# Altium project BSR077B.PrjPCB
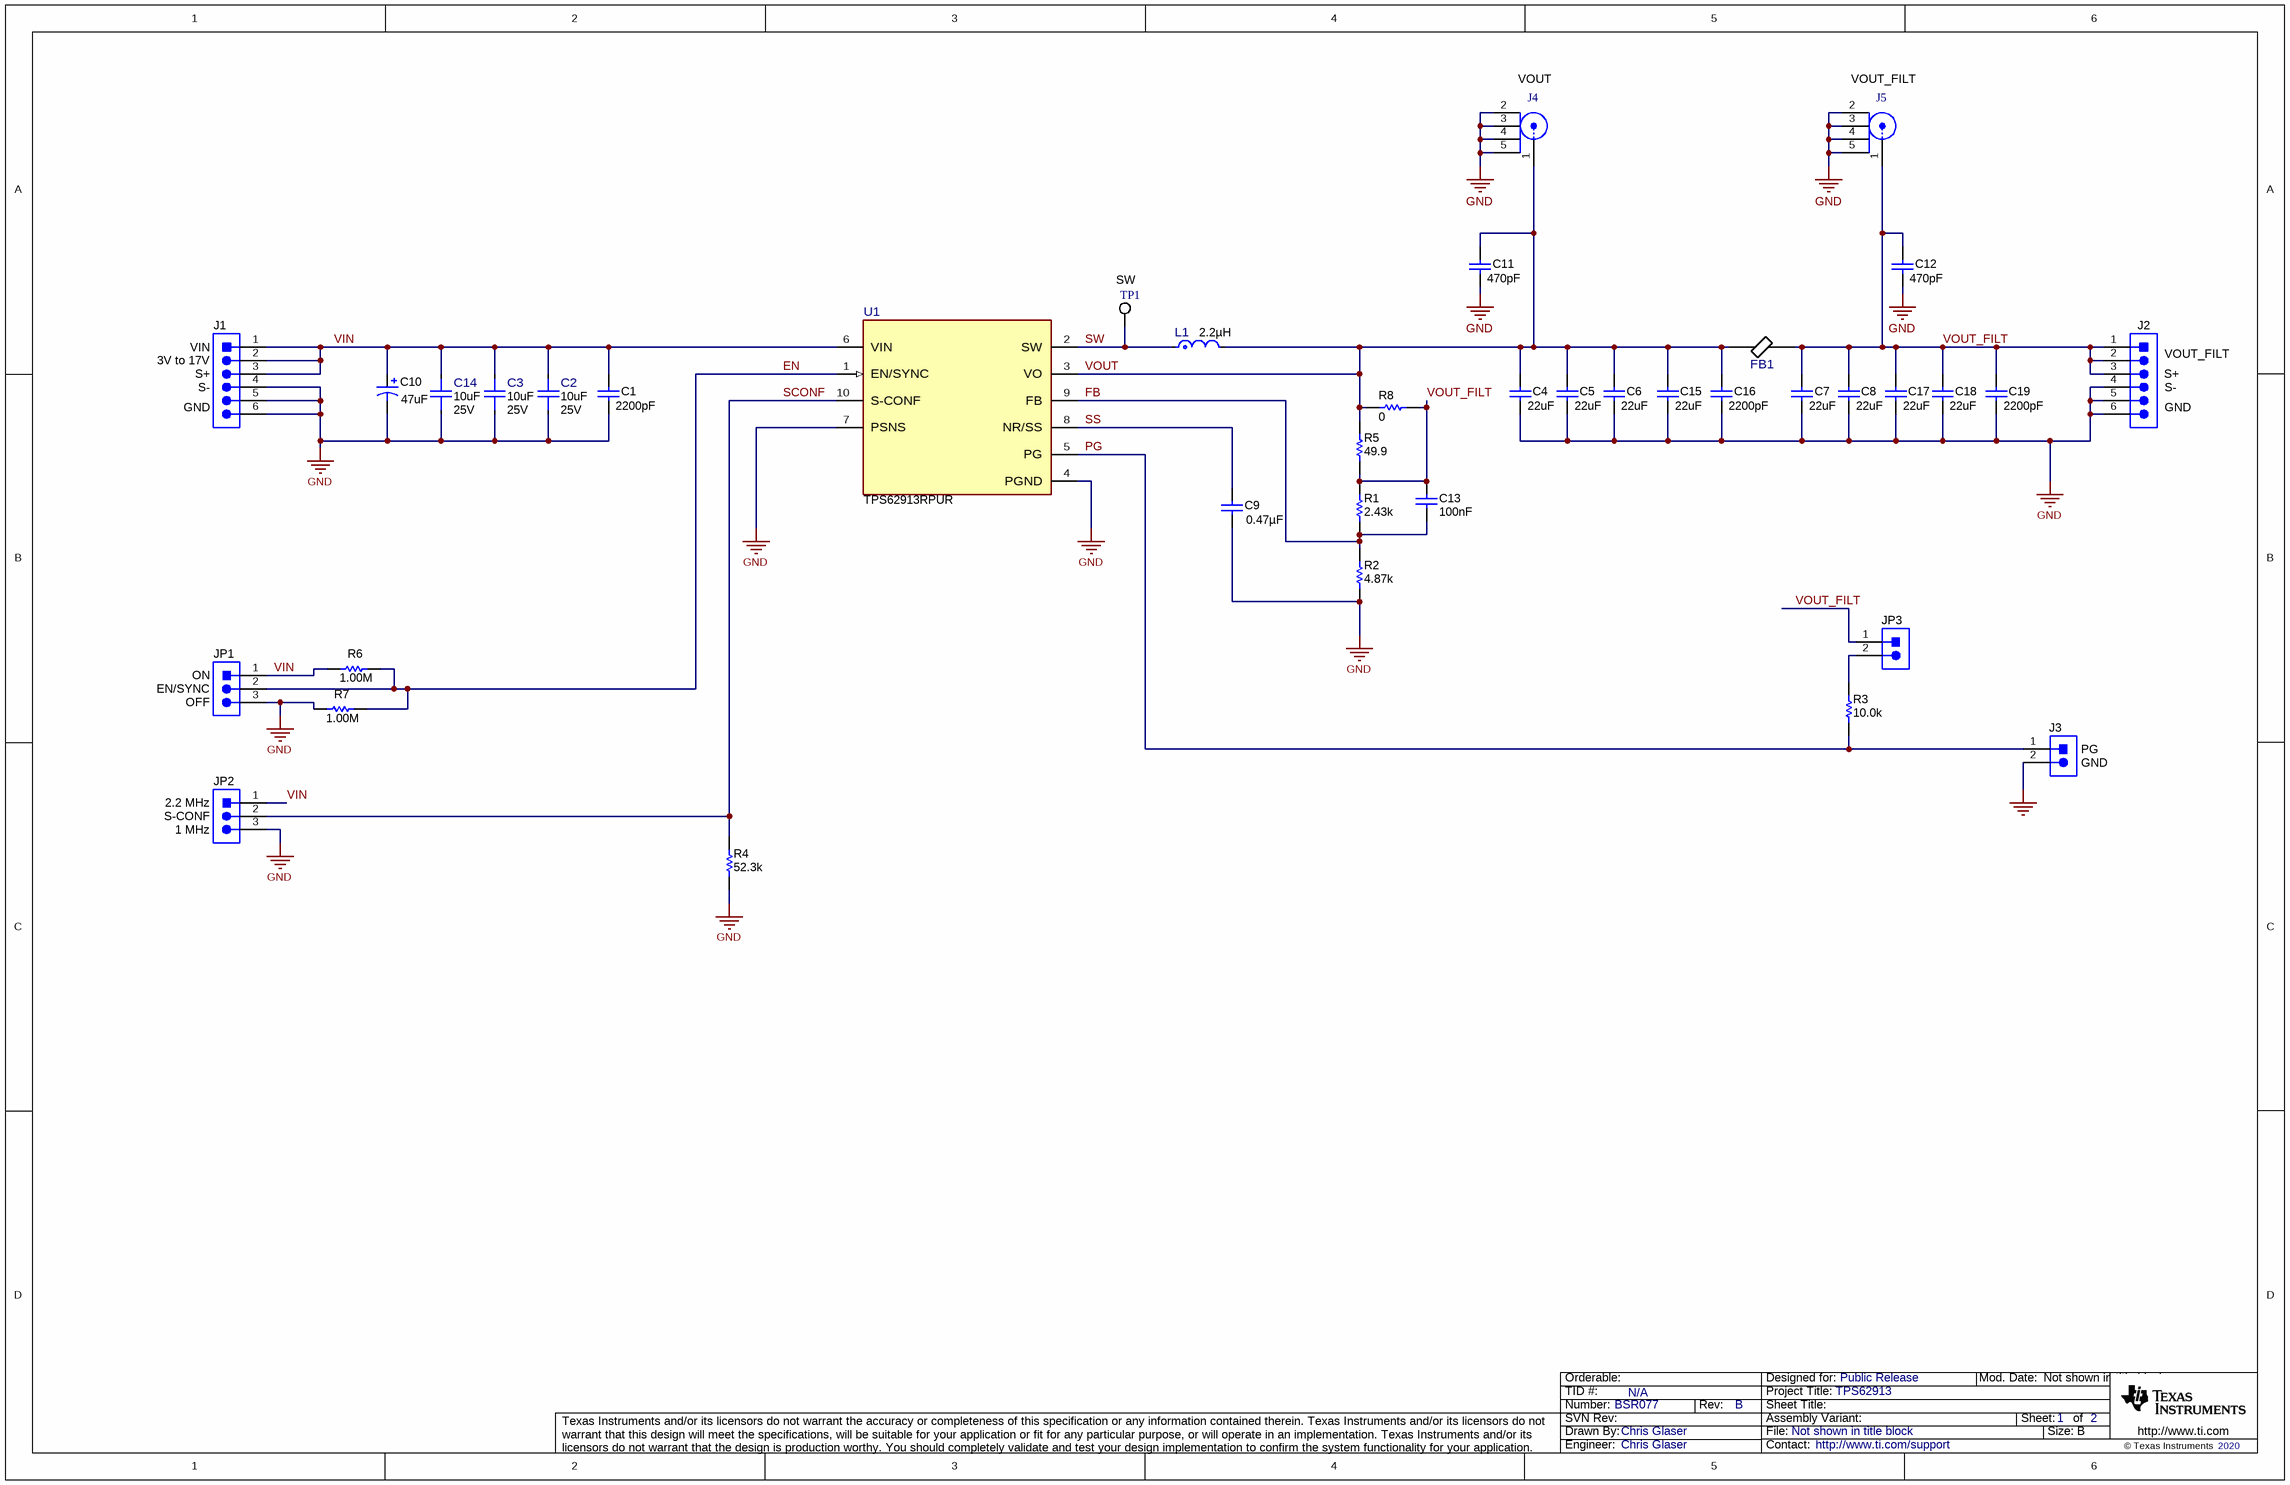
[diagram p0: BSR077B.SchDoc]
CopyrightYear: 2020; PCB_Layout: Fred Illguth; PCB_Rev: B; PRJ_Customer: Public Release; PRJ_Engineer: Chris Glaser; PRJ_Number: BSR077; PRJ_Title: TPS62913; SCH_Rev: B; TechSupport: http://www.ti.com/support; TID: N/A
2 sheets, 59 parts. Net scope: global (net labels, ports and power ports of the same name join across sheets).
Board file: BSR077B.PcbDoc
Sheets:
  BSR077B.SchDoc
  BSR077B_Hardware.SchDoc

## Sheet BSR077B.SchDoc
size 431 x 279 mm; Date: Not shown in title block; ApprovedBy: Not shown in title block; CheckedBy: Not shown in title block; Author: Not shown in title block; CompanyName: Not shown in title block; DrawnBy: Chris Glaser; Engineer: Not shown in title block; Organization: Not shown in title block; Address1: Not shown in title block; Address2: Not shown in title block; Address3: Not shown in title block; Address4: Not shown in title block; DocumentNumber: 2; Revision: Use project parameter SCH_Rev; SheetNumber: 1; SheetTotal: 2; PageSetup: Record=PageOptions¦CenterHorizontal=True¦CenterVertical=True¦PrintScale=1.00¦XCorrection=1.00¦YCorrection=1.00¦PrintKind=0¦BorderSize=5000000¦LeftOffset=0¦BottomOffset=0¦Orientation=2¦PaperLength=1000¦PaperWidth=1000¦Scale=100¦PaperSource=15¦PrintQuality=600¦MediaType=1¦DitherType=10¦PaperKind=Letter¦PrintScaleMode=1

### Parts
C1  ValueDisplayed: 2200pF  [0402S]  (hidden comment: GRM155R71H222KA01D)
C2  ValueDisplayed: 10uF  VDC_V: 25V  [0805_HV1]  (hidden comment: C2012X7S1E106K125AC)
C3  ValueDisplayed: 10uF  VDC_V: 25V  [0805_HV1]  (hidden comment: C2012X7S1E106K125AC)
C4  ValueDisplayed: 22uF  [0805_HV1]  (hidden comment: C2012X7S1A226M125AC)
C5  ValueDisplayed: 22uF  [0805_HV1]  (hidden comment: C2012X7S1A226M125AC)
C6  ValueDisplayed: 22uF  [0805_HV1]  (hidden comment: C2012X7S1A226M125AC)
C7  ValueDisplayed: 22uF  [0805_HV1]  (hidden comment: C2012X7S1A226M125AC)
C8  ValueDisplayed: 22uF  [0805_HV1]  (hidden comment: C2012X7S1A226M125AC)
C9  ValueDisplayed: 0.47µF  [0603S]  (hidden comment: C1608X7R1E474K080AE)
C10  ValueDisplayed: 47uF  [7343-43]  (hidden comment: T495X476K035ATE300)
C11  ValueDisplayed: 470pF  [0402S]  (hidden comment: GRM1555C1H471JA01D)
C12  ValueDisplayed: 470pF  [0402S]  (hidden comment: GRM1555C1H471JA01D)
C13  Cap_F: 100nF  [0603S]  (hidden comment: 885012206046)
C14  ValueDisplayed: 10uF  VDC_V: 25V  [0805_HV1]  (hidden comment: C2012X7S1E106K125AC)
C15  ValueDisplayed: 22uF  [0805_HV1]  (hidden comment: C2012X7S1A226M125AC)
C16  ValueDisplayed: 2200pF  [0402S]  (hidden comment: GRM155R71H222KA01D)
C17  ValueDisplayed: 22uF  [0805_HV1]  (hidden comment: C2012X7S1A226M125AC)
C18  ValueDisplayed: 22uF  [0805_HV1]  (hidden comment: C2012X7S1A226M125AC)
C19  ValueDisplayed: 2200pF  [0402S]  (hidden comment: GRM155R71H222KA01D)
FB1  BLE18PS080SN1  [FP-BLE18PS080SN1_0603-MFG]  (value not drawn)
J1  TSW-106-07-G-S  [TSW-106-07-G-S]  (value not drawn)
J2  TSW-106-07-G-S  [TSW-106-07-G-S]  (value not drawn)
J3  TSW-102-07-G-S  [TSW-102-07-G-S]  (value not drawn)
J4  60312002114503  [FP-60312002114503_CONN_SMA_PTH-MFG]  (value not drawn)
J5  60312002114503  [FP-60312002114503_CONN_SMA_PTH-MFG]  (value not drawn)
JP1  TSW-103-07-G-S  [TSW-103-07-G-S]  (value not drawn)
JP2  TSW-103-07-G-S  [TSW-103-07-G-S]  (value not drawn)
JP3  TSW-102-07-G-S  [TSW-102-07-G-S]  (value not drawn)
L1  value 2.2µH  [FP-XGL4030-222MEC_SMT_IND_4MM0_4MM0-MFG]  (hidden comment: XGL4030-222MEC)
R1  ValueDisplayed: 2.43k  [0603S]  (hidden comment: CRCW06032K43FKEA)
R2  ValueDisplayed: 4.87k  [0603S]  (hidden comment: RC0603FR-074K87L)
R3  ValueDisplayed: 10.0k  [0603]  (hidden comment: RC0603FR-0710KL)
R4  ValueDisplayed: 52.3k  [0603S]  (hidden comment: RC0603FR-0752K3L)
R5  ValueDisplayed: 49.9  [0603]  (hidden comment: ERJ-3EKF49R9V)
R6  ValueDisplayed: 1.00M  [0603]  (hidden comment: RC0603FR-071ML)
R7  ValueDisplayed: 1.00M  [0603]  (hidden comment: RC0603FR-071ML)
R8  ValueDisplayed: 0  [0603]  (hidden comment: RCS06030000Z0EA)
TP1  5002  [Keystone5002]  (value not drawn)
U1  TPS62913RPUR  [RPU0010A-MFG]

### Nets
GND: C1.2 C2.1 C3.1 C4.2 C5.2 C6.2 C7.2 C8.2 C9.2 C10.2(-) C11.2 C12.2 C14.1 C15.2 C16.2 C17.2 C18.2 C19.2 J1.4 J1.5 J1.6 J2.4 J2.5 J2.6 J3.2 J4.2 J4.3 J4.4 J4.5 J5.2 J5.3 J5.4 J5.5 JP1.3 JP2.3 R2.1 R4.1 R7.1 U1.4(PGND) U1.7(PSNS)
EN: JP1.2 R6.2 R7.2 U1.1(EN/SYNC)
FB: C13.2 R1.1 R2.2 U1.9(FB)
PG: J3.1 R3.1 U1.5(PG)
SCONF: JP2.2 R4.2 U1.10(S-CONF)
SS: C9.1 U1.8(NR/SS)
SW: L1.1 TP1.1 U1.2(SW)
VIN: C1.1 C2.2 C3.2 C10.1(+) C14.2 J1.1 J1.2 J1.3 JP1.1 JP2.1 R6.1 U1.6(VIN)
VOUT: C4.1 C5.1 C6.1 C11.1 C15.1 C16.1 FB1.1 J4.1 L1.2 R5.2 R8.1 U1.3(VO)
VOUT_FILT: C7.1 C8.1 C12.1 C13.1 C17.1 C18.1 C19.1 FB1.2 J2.1 J2.2 J2.3 J5.1 JP3.1 R1.2 R5.1 R8.2
NetJP3_2: JP3.2 R3.2

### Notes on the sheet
- (near J4) VOUT
- (near J5) VOUT_FILT
- (near TP1) SW
- (near J1) 3V to 17V
- (near J1) VIN
- (near J2) VOUT_FILT
- (near J1) GND
- (near J1) S+
- (near J1) S-
- (near J2) S-
- (near J2) S+
- (near J2) GND
- (near JP1) EN/SYNC
- (near JP1) OFF
- (near JP1) ON
- (near J3) PG
- (near J3) GND
- (near JP2) S-CONF
- (near JP2) 2.2 MHz
- (near JP2) 1 MHz

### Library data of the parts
C1 C16 C19 = CMP-0006683-2: CAP, CERM, 2200 pF, 50 V, +/- 10%, X7R, 0402; Manufacturer: MuRata; TaMin_C: -55°C; Polarized: N; SizeAreaWB_mm2: 3; Value1: Unknown; U/M: EA; Value: 2200pF; TaMax_C: 125°C; SizeZ_mm: 0.6; SizeX_mm: 1; SizeY_mm: 0.5; Cap_Case: 0402; Value2: 50V; Cap_F: 2.2nF; AEC Category: Q200
C2 C3 C14 = CMP-0089528-3: 10µF ±10% 25V Ceramic Capacitor X7S 0805 (2012 Metric); Manufacturer: TDK; SizeZ_mm: 1.5mm; AEC Qualified: No; TempCo: 22%
C4-C8 C15 C17 C18 = CMP-0007890-2: CAP, CERM, 22 uF, 10 V, +/- 20%, X7S, 0805; Manufacturer: TDK; TaMin_C: -55°C; ESR_ohm: 2.05m; Polarized: N; SizeAreaWB_mm2: 6.75; Value1: 0.00205 ohm; U/M: EA; Value: 22uF; TaMax_C: 125°C; SizeZ_mm: 1.45; SizeX_mm: 2; SizeY_mm: 1.25; Cap_Case: 0805; Value2: 10V; SizeArea_mm2: 2.5; Cap_F: 22µF; IRMS_A: 4.55587A; AEC Category: Q200
C9 = CMP-0750175-1: CAP, CERM, 0.47 µF, 25 V,+/- 10%, X7R, 0603; Manufacturer: TDK; AEC Qualified: N; TaMax_C: 125°C; Cap_F: 470nF; VDC_V: 25V; U/M: EA; AEC Category: Q200; Value: 0.47uF; SizeX_mm: 1.6; SizeAreaWB_mm2: 4.68; SizeZ_mm: 1; SizeY_mm: 0.8; SizeArea_mm2: 1.28; TaMin_C: -55°C; Cap_Case: 0603
C10 = CMP-0011835-2: CAP, TA, 47 uF, 35 V, +/- 10%, 0.3 ohm, SMD; Manufacturer: Kemet; TaMin_C: -55°C; ESR_ohm: 0.3; Polarized: Y; SizeAreaWB_mm2: 58.59; Value1: 0.3 ohm; U/M: EA; Value: 47uF; TaMax_C: 125°C; SizeZ_mm: 4.3; SizeX_mm: 7.3; Cap_Case: X; Value2: 35V; SizeArea_mm2: 31.39; CompType: Capacitor; Cap_F: 47µF; IRMS_A: 667mA; AEC Category: Q200
C11 C12 = CMP-0006470-2: CAP, CERM, 470 pF, 50 V, +/- 5%, C0G/NP0, 0402; Manufacturer: MuRata; TaMin_C: -55°C; Polarized: N; SizeAreaWB_mm2: 3; Value1: Unknown; U/M: EA; Value: 470pF; TaMax_C: 125°C; SizeZ_mm: 0.6; SizeX_mm: 1; SizeY_mm: 0.5; Cap_Case: 0402; Value2: 50V; AEC Category: Q200
C13 = CMP-0006829-4: CAP, CERM, 0.1 uF, 16 V, +/- 10%, X7R, 0603; Manufacturer: Wurth Elektronik; TaMin_C: -55°C; Polarized: N; SizeAreaWB_mm2: 4.68; Value1: Unknown; U/M: EA; Value: 0.1uF; TaMax_C: 125°C; SizeZ_mm: 1; SizeX_mm: 1.6; SizeY_mm: 0.8; Cap_Case: 0603; Value2: 16V; SizeArea_mm2: 1.28; AEC Category: Q200
FB1 = CMP-0087072-1: Bead inductor BLE series, 8A; Manufacturer: Murata; AEC Qualified: No; SizeZ_mm: 0.75mm; Material: Ferrite
J1 J2 = CMP-0075413-2: Header, 100mil, 6x1, Gold, TH; Manufacturer: Samtec; Pitch_mm: 2.54; Gender: Male; Shrouded: N; Row_Count: 1; Current_A: 6.3A; Voltage_V: 550V; Cert_CSA: Y; Green_Lifecycle: Active; Green_REACh: Passed
J3 JP3 = CMP-0075405-3: Header, 100mil, 2x1, Gold, TH; Manufacturer: Samtec; Pitch_mm: 2.54; Gender: Male; Shrouded: N; Row_Count: 1; Current_A: 6.3A; Voltage_V: 550V; Cert_CSA: Y; Green_Lifecycle: Active; Green_REACh: Passed
J4 J5 = CMP-0089038-2: SMA Connector Jack, Female Socket 50Ohm Through Hole Solder; Manufacturer: Wurth Electronics; Voltage_V: 335V; ContactFinish: Gold,Nickel; Shrouded: true
JP1 JP2 = CMP-0075407-2: Header, 100mil, 3x1, Gold, TH; Manufacturer: Samtec; Pitch_mm: 2.54; Gender: Male; Shrouded: N; Row_Count: 1; Current_A: 6.3A; Voltage_V: 550V; Cert_CSA: Y; Green_Lifecycle: Active; Green_REACh: Passed
L1 = CMP-0089541-3: Inductor Power Shielded Wirewound 2.2uH 20% 1MHz Composite 8.7A 15mOhm DCR Automotive T/R; Manufacturer: Coilcraft; Shrouded: true; SizeZ_mm: 3.1mm; AEC Grade: Grade 1; AEC Qualified: Yes; Isat: 3.1A; Self Resonant Frequency: 40MHz; DCR_ohm: 0.015; Standoff Height: 0.16mm; TaMin_C: -40°C; TaMax_C: +125°C
R1 = CMP-0022276-4: RES, 2.43 k, 1%, 0.1 W, AEC-Q200 Grade 0, 0603; Manufacturer: Vishay-Dale; Power_W: 100mW; TempCo: 100 ppm/C; Value_Code: 2k43; Value: 2.43k; EIA_Code: E96; SizeX_mm: 1.6; SizeY_mm: 0.8; SizeZ_mm: 1; Value2: 0.1W; SizeArea_mm2: 1.28; AEC Qualified: Y; VDC_V: 75V; AEC Category: Q200; AEC Grade: 0
R2 = CMP-0023154-5: RES, 4.87 k, 1%, 0.1 W, 0603; Manufacturer: Yageo; Power_W: 100mW; TempCo: 100 ppm/C; Value_Code: 4k87; Value: 4.87k; EIA_Code: E96; SizeX_mm: 1.6; SizeY_mm: 0.8; SizeZ_mm: 1; Value2: 0.1W; SizeArea_mm2: 1.28; AEC Qualified: N; VDC_V: 75V; AEC Category: Q200; SizeAreaWB_mm2: 4.68
R3 = CMP-0022746-5: RES, 10.0 k, 1%, 0.1 W, 0603; Manufacturer: Yageo; Power_W: 100mW; TempCo: 100 ppm/C; Value_Code: 10k0; Value: 10.0k; EIA_Code: E96; Res_ohm: 10k; SizeX_mm: 1.6; SizeY_mm: 0.8; SizeZ_mm: 1; Value2: 0.1W; SizeArea_mm2: 1.28; AEC Qualified: N; VDC_V: 75V; AEC Category: Q200; SizeAreaWB_mm2: 4.68
R4 = CMP-0023172-5: RES, 52.3 k, 1%, 0.1 W, 0603; Manufacturer: Yageo; Power_W: 100mW; TempCo: 100 ppm/C; Value_Code: 52k3; Value: 52.3k; EIA_Code: E96; SizeX_mm: 1.6; SizeY_mm: 0.8; SizeZ_mm: 1; Value2: 0.1W; SizeArea_mm2: 1.28; AEC Qualified: N; VDC_V: 75V; AEC Category: Q200; SizeAreaWB_mm2: 4.68
R5 = CMP-0022707-2: RES, 49.9, 1%, 0.1 W, AEC-Q200 Grade 0, 0603; Manufacturer: Panasonic; Power_W: 100mW; Value_Code: 49R9; U/M: EA; Value: 49.9; EIA_Code: E96; TempCo: 100 ppm/C; SizeX_mm: 1.6; SizeY_mm: 0.8; SizeZ_mm: 1; Value2: 0.1W; SizeArea_mm2: 1.28; AEC Qualified: Y; AEC Grade: 0; AEC Category: Q200
R6 R7 = CMP-0022899-4: RES, 1.00 M, 1%, 0.1 W, 0603; Manufacturer: Yageo; Power_W: 100mW; TempCo: 100 ppm/C; Value_Code: 1M00; Value: 1.00Meg; EIA_Code: E96; Res_ohm: 1M; SizeX_mm: 1.6; SizeY_mm: 0.8; SizeZ_mm: 1; Value2: 0.1W; SizeArea_mm2: 1.28; AEC Qualified: N; VDC_V: 75V; AEC Category: Q200; SizeAreaWB_mm2: 4.68
R8 = CMP-0081973-1: RES, 0, 0%, 0.25 W, AEC-Q200 Grade 0, 0603; Manufacturer: Vishay-Dale; SizeAreaWB_mm2: 4.68; SizeArea_mm2: 1.28; AEC Qualified: Y; AEC Category: Q200; Value: 0; SizeZ_mm: 1; SizeY_mm: 0.8; Power_W: 250mW; Value2: 0.25W; SizeX_mm: 1.6
TP1 = CMP-0055139-1: Test Point, Miniature, White, TH; Manufacturer: Keystone; CNHeader: FALSE; Green_Lifecycle: Active; Green_REACh: Passed; ContactFinish: Silver; CT: TRUE
U1 = CMP-0089785-1: 3V to 17V, 3A Micro Noise (20µVRMS) and Micro Ripple (200µVPP) buck converter; Manufacturer: Texas Instruments; SizeZ_mm: 1mm; TJmax_C: +150°C; Output Type: AdjustableProgrammable; Switching Frequency: 1/2.2MHz; Max Duty Cycle: 55%; Number Of Outputs: 1; Nominal Supply Current: 5mA; AEC Qualified: No; Output Voltage: 0.8-5.5V; Standoff Height: 0mm

## Sheet BSR077B_Hardware.SchDoc
size 431 x 279 mm; Date: Not shown in title block; ApprovedBy: Not shown in title block; CheckedBy: Not shown in title block; Author: Not shown in title block; CompanyName: Not shown in title block; DrawnBy: Chris Glaser; Engineer: Not shown in title block; Organization: Not shown in title block; Address1: Not shown in title block; Address2: Not shown in title block; Address3: Not shown in title block; Address4: Not shown in title block; DocumentNumber: 3; Revision: Use project parameter SCH_Rev; SheetNumber: 2; SheetTotal: 2; PageSetup: Record=PageOptions¦CenterHorizontal=True¦CenterVertical=True¦PrintScale=1.00¦XCorrection=1.00¦YCorrection=1.00¦PrintKind=0¦BorderSize=5000000¦LeftOffset=0¦BottomOffset=0¦Orientation=2¦PaperLength=1000¦PaperWidth=1000¦Scale=100¦PaperSource=15¦PrintQuality=600¦MediaType=1¦DitherType=10¦PaperKind=Letter¦PrintScaleMode=1
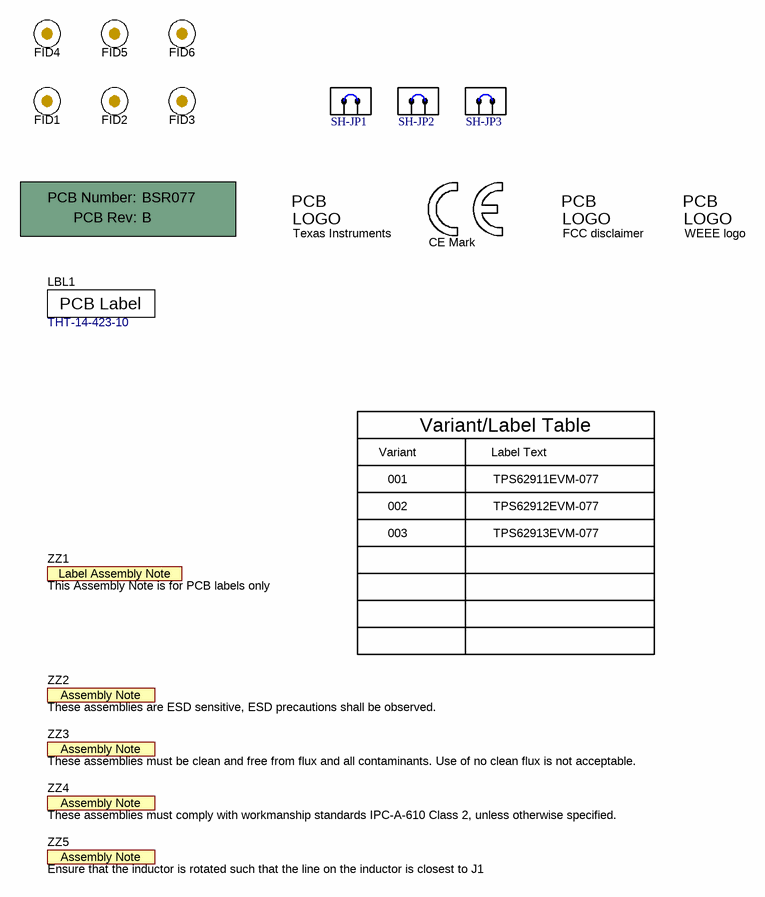
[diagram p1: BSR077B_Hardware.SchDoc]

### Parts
!PCB  Printed Circuit Board  (value not drawn)  (mechanical)
FID1  Fiducial  [Fiducial10-20]  (value not drawn)
FID2  Fiducial  [Fiducial10-20]  (value not drawn)
FID3  Fiducial  [Fiducial10-20]  (value not drawn)
FID4  Fiducial  [Fiducial10-20]  (value not drawn)
FID5  Fiducial  [Fiducial10-20]  (value not drawn)
FID6  Fiducial  [Fiducial10-20]  (value not drawn)
LBL1  THT-14-423-10  [Label_650x200]
Logo1  Texas Instruments  [TI_Stacked_Overlay_Small]  (no BOM)
Logo2  CE Mark  [CE_Mark_5mm]  (no BOM)
Logo3  FCC disclaimer  [FCC_disclaimer]  (no BOM)
Logo4  WEEE logo  [WEEE_Minimum]  (no BOM)
SH-JP1  60900213421  [Wurth_60900213421]  (value not drawn)
SH-JP2  60900213421  [Wurth_60900213421]  (value not drawn)
SH-JP3  60900213421  [Wurth_60900213421]  (value not drawn)
ZZ1  This Assembly Note is for PCB labels only  [AssemblyNoteLabel]  (no BOM)
ZZ2  These assemblies are ESD sensitive, ESD precautions shall be observed.  [AssemblyNote]  (no BOM)
ZZ3  These assemblies must be clean and free from flux and all contaminants. Use of no clean flux is not acceptable.  [AssemblyNote]  (no BOM)
ZZ4  These assemblies must comply with workmanship standards IPC-A-610 Class 2, unless otherwise specified.  [AssemblyNote]  (no BOM)
ZZ5  Ensure that the inductor is rotated such that the line on the inductor is closest to J1  [AssemblyNote]  (no BOM)

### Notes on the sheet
- Variant
- Variant/Label Table
- Label Text
- 001
- 002
- TPS62912EVM-077
- TPS62911EVM-077
- 003
- TPS62913EVM-077

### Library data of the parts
!PCB = CMP-0003618-2: Manufacturer: Any; PartNumber: BSR077
FID1-FID6 = CMP-0077181-1: Fiducial mark.  There is nothing to buy or mount.
LBL1 = CMP-0003625-1: Thermal Transfer Printable Labels, 0.650" W x 0.200" H - 10,000 per roll; Manufacturer: Brady; Note: Size: 0.65" x 0.20 "
Logo1 = CMP-0074838-1: Texas Instrument Corporate Signature; SymbolCreator: a0412235; Lib Reference: TI_Logo; Library Reference: Logo
Logo2 = CMP-0074844-1: SymbolCreator: a0412235
Logo3 = CMP-0074847-1: FCC_disclaimer; Library Reference: Logo
Logo4 = CMP-0074769-1
SH-JP1-SH-JP3 = CMP-0003761-2: Shunt, 2.54mm, Gold, Black; Manufacturer: Wurth Elektronik
ZZ1 = CMP-0003616-3
ZZ2 = CMP-0077236-1
ZZ3 = CMP-0077237-1
ZZ4 = CMP-0077238-1
ZZ5 = CMP-0077238-1: Special instruction for inductor L1 assembly

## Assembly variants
001: not fitted C13 C14 C15 C16 C17 C18 C19 FID1 FID2 FID3 FID4 FID5 FID6 R5 R6 R7 R8 TP1; alternate parts R4 -> CMP-0022965-5, R1 -> CMP-0022814-5, U1 -> CMP-0089784-1
002: not fitted C13 C14 C15 C16 C17 C18 C19 FID1 FID2 FID3 FID4 FID5 FID6 R5 R6 R7 R8 TP1; alternate parts R4 -> CMP-0022965-5, R1 -> CMP-0022814-5, U1 -> CMP-0089784-1
003: not fitted C13 C14 C15 C16 C17 C18 C19 FID1 FID2 FID3 FID4 FID5 FID6 R5 R6 R7 R8 TP1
